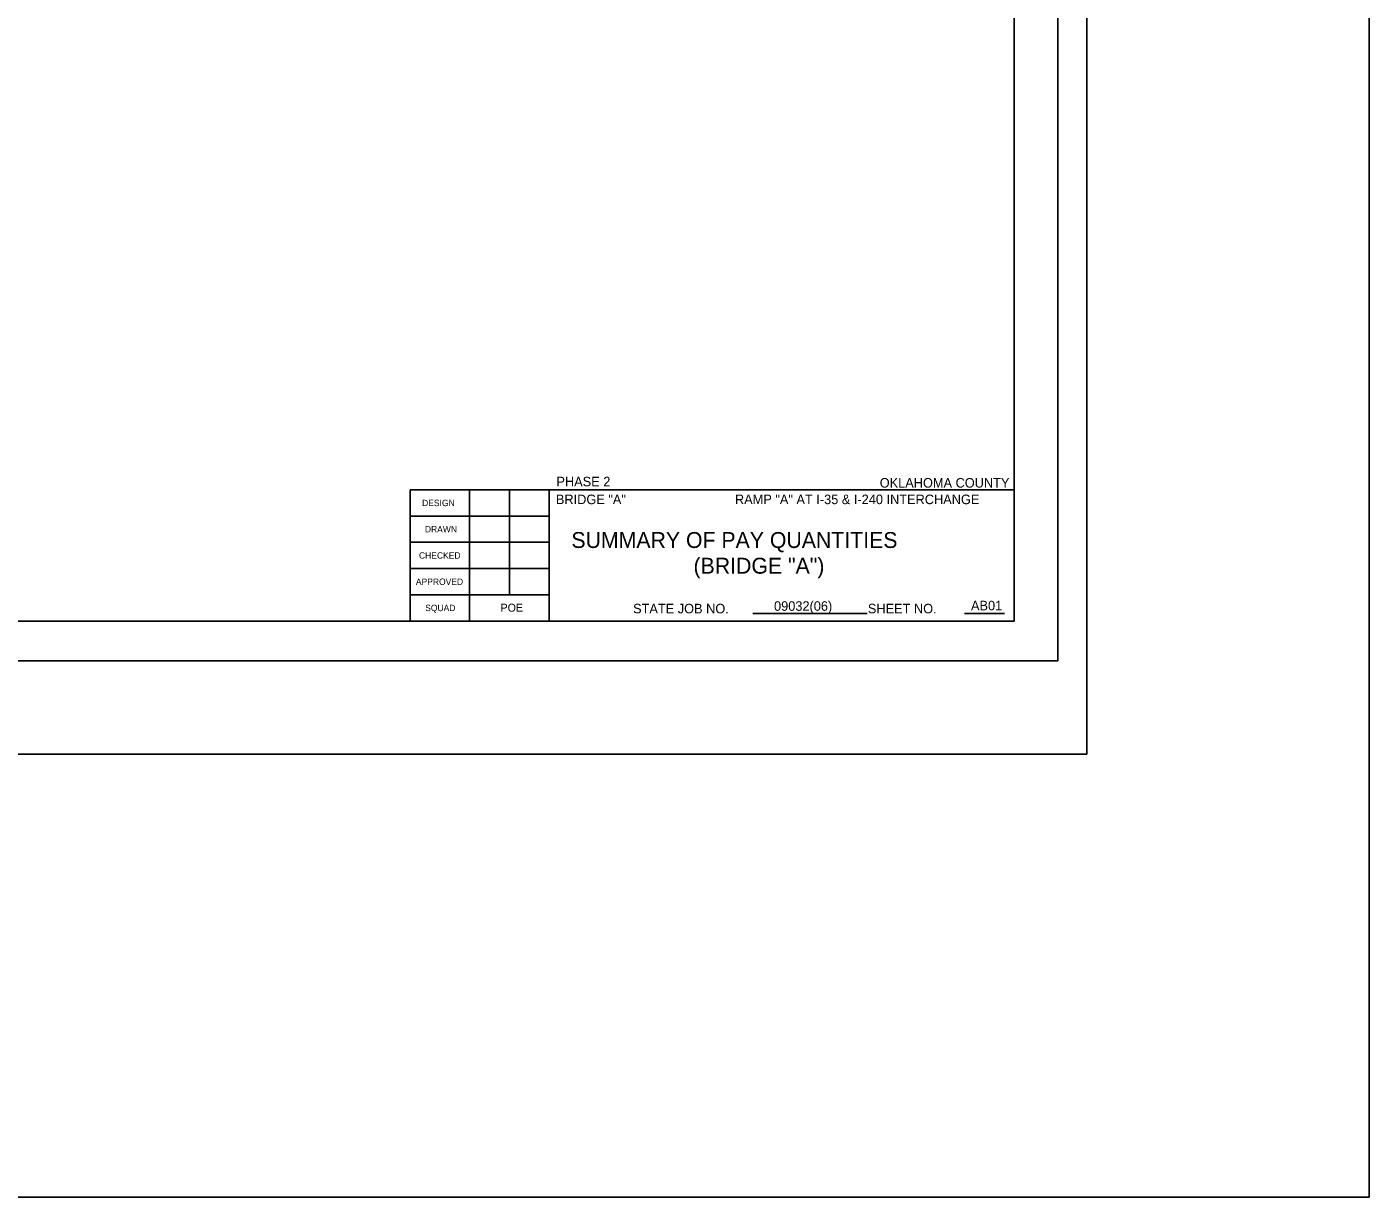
# Model space of a CAD drawing. Extents: x 12306 to 12361.5, y 578.9 to 640.4.
# Drawn here: x 12339.03 to 12355.91, y 578.9 to 593.62 of the extents above; entities that cross this region are included whole.
import ezdxf

# ---------------------------------------------------------------- set-up
doc = ezdxf.new("R2010")
doc.units = 0
for name, color, linetype in [('S', 7, 'Continuous'), ('SHT_Plot_Shape_Full', 7, 'Continuous'), ('SHT_Plot_Shape_Half', 7, 'Continuous'), ('SHT_Sheet_Border', 7, 'Continuous'), ('SHT_Standard_Sheet_Lines', 7, 'Continuous'), ('SHT_Standard_Sheet_Txt', 7, 'Continuous'), ('T', 7, 'Continuous'), ('T-Title', 7, 'Continuous')]:
    doc.layers.add(name, color=color, linetype=linetype)

msp = doc.modelspace()

# ---------------------------------------------------------------- linework, layer by layer
at = {"layer": 'S'}
msp.add_lwpolyline([(12355.912, 640.357), (12312.476, 640.357), (12312.476, 578.901), (12355.912, 578.901)], close=True, dxfattribs=at)
at = {"layer": 'SHT_Plot_Shape_Full'}
msp.add_lwpolyline([(12316.36, 608.469), (12352.36, 608.469), (12352.36, 584.469), (12316.36, 584.469)], close=True, dxfattribs=at)
at = {"layer": 'SHT_Plot_Shape_Half'}
msp.add_lwpolyline([(12317.998, 607.644), (12351.998, 607.644), (12351.998, 585.644), (12317.998, 585.644)], close=True, dxfattribs=at)
at = {"layer": 'SHT_Sheet_Border'}
for p, q in [((12343.848, 587.794), (12351.448, 587.795)), ((12343.848, 586.144), (12343.848, 587.794)), ((12345.598, 586.144), (12345.598, 587.795))]:
    msp.add_line(p, q, dxfattribs=at)
msp.add_lwpolyline([(12351.448, 586.144), (12319.948, 586.144), (12319.948, 607.144), (12351.448, 607.144)], close=True, dxfattribs=at)
at = {"layer": 'SHT_Standard_Sheet_Lines'}
for p, q in [((12344.598, 586.144), (12344.598, 587.795)), ((12345.098, 586.475), (12345.098, 587.795)), ((12348.159, 586.241), (12349.599, 586.241)), ((12350.823, 586.241), (12351.326, 586.241))]:
    msp.add_line(p, q, dxfattribs=at)
for points in [[(12345.598, 587.464), (12343.848, 587.464)], [(12345.598, 587.134), (12343.848, 587.134)], [(12345.598, 586.804), (12343.848, 586.804)], [(12345.598, 586.474), (12343.848, 586.474)]]:
    msp.add_lwpolyline(points, dxfattribs=at)

# ---------------------------------------------------------------- texts
at = {"layer": 'SHT_Standard_Sheet_Txt'}
for s, height, p in [('DESIGN', 0.08, (12344, 587.589)), ('DRAWN', 0.08, (12344.035, 587.259)), ('CHECKED', 0.08, (12343.961, 586.929)), ('APPROVED', 0.08, (12343.922, 586.599)), ('SQUAD', 0.08, (12344.039, 586.269)), ('STATE JOB NO.', 0.12, (12346.654, 586.241)), ('SHEET NO. ', 0.12, (12349.607, 586.241))]:
    msp.add_text(s, height=height, dxfattribs=at).set_placement(p)
at = {"layer": 'T'}
for s, height, p in [('PHASE 2', 0.12, (12345.69, 587.838)), ('OKLAHOMA COUNTY', 0.12, (12349.756, 587.822)), ('BRIDGE "A"', 0.12, (12345.683, 587.614)), ('RAMP "A" AT I-35 & I-240 INTERCHANGE', 0.12, (12347.935, 587.614)), ('POE', 0.1, (12344.987, 586.262)), ('09032(06)', 0.12, (12348.427, 586.273)), ('AB01', 0.12, (12350.904, 586.279))]:
    msp.add_text(s, height=height, dxfattribs=at).set_placement(p)
at = {"layer": 'T-Title'}
for s, p in [('SUMMARY OF PAY QUANTITIES', (12345.878, 587.063)), ('(BRIDGE "A")', (12347.414, 586.74))]:
    msp.add_text(s, height=0.2, dxfattribs=at).set_placement(p)

doc.saveas('drawing.dxf')
